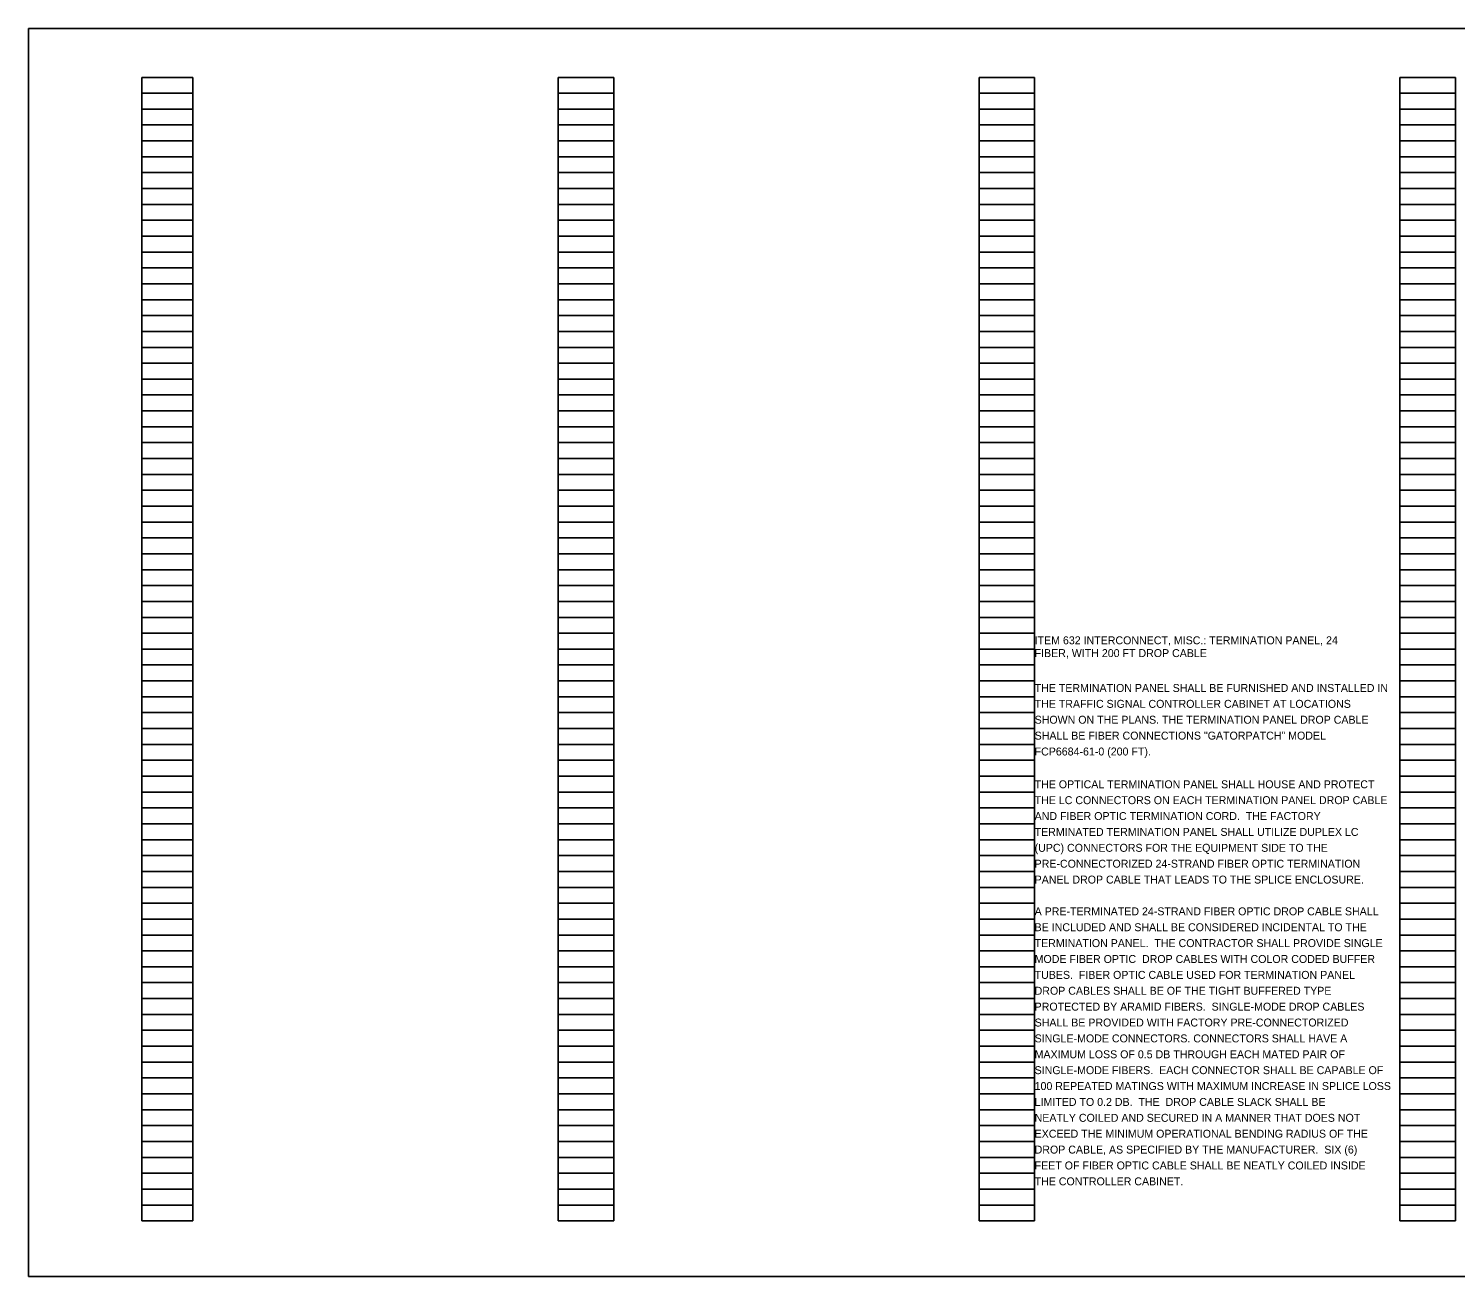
# Model space of a CAD drawing. Extents: x -36.9 to 49.6, y -47.1 to 37.
# Drawn here: x -0.51 to 24.65, y -47.06 to -25.06 of the extents above; entities that cross this region are included whole.
import ezdxf

# ---------------------------------------------------------------- set-up
doc = ezdxf.new("R2010")
doc.units = 0
for name, color, linetype in [('SC_Scratch1', 7, 'Continuous'), ('SH_Cut_Line', 7, 'Continuous'), ('SH_Data', 7, 'Continuous'), ('SH_Text', 7, 'Continuous')]:
    doc.layers.add(name, color=color, linetype=linetype)

msp = doc.modelspace()

# ---------------------------------------------------------------- linework, layer by layer
at = {"layer": 'SC_Scratch1'}
for p, q in [((1.494, -46.083), (1.494, -25.923)), ((1.494, -25.923), (2.394, -25.923)), ((2.394, -46.083), (2.394, -25.923)), ((8.834, -46.083), (8.834, -25.923)), ((8.834, -25.923), (9.814, -25.923)), ((9.814, -46.083), (9.814, -25.923)), ((16.254, -46.083), (16.254, -25.923)), ((16.254, -25.923), (17.234, -25.923)), ((17.234, -46.083), (17.234, -25.923)), ((23.674, -46.083), (23.674, -25.923)), ((23.674, -25.923), (24.654, -25.923)), ((24.654, -46.083), (24.654, -25.923)), ((1.494, -26.203), (2.394, -26.203)), ((8.834, -26.203), (9.814, -26.203)), ((16.254, -26.203), (17.234, -26.203)), ((23.674, -26.203), (24.654, -26.203)), ((1.494, -26.483), (2.394, -26.483)), ((8.834, -26.483), (9.814, -26.483)), ((16.254, -26.483), (17.234, -26.483)), ((23.674, -26.483), (24.654, -26.483)), ((1.494, -26.763), (2.394, -26.763)), ((8.834, -26.763), (9.814, -26.763)), ((16.254, -26.763), (17.234, -26.763)), ((23.674, -26.763), (24.654, -26.763)), ((1.494, -27.043), (2.394, -27.043)), ((8.834, -27.043), (9.814, -27.043)), ((16.254, -27.043), (17.234, -27.043)), ((23.674, -27.043), (24.654, -27.043)), ((1.494, -27.323), (2.394, -27.323)), ((8.834, -27.323), (9.814, -27.323)), ((16.254, -27.323), (17.234, -27.323)), ((23.674, -27.323), (24.654, -27.323)), ((1.494, -27.603), (2.394, -27.603)), ((8.834, -27.603), (9.814, -27.603)), ((16.254, -27.603), (17.234, -27.603)), ((23.674, -27.603), (24.654, -27.603)), ((1.494, -27.883), (2.394, -27.883)), ((8.834, -27.883), (9.814, -27.883)), ((16.254, -27.883), (17.234, -27.883)), ((23.674, -27.883), (24.654, -27.883)), ((1.494, -28.163), (2.394, -28.163)), ((8.834, -28.163), (9.814, -28.163)), ((16.254, -28.163), (17.234, -28.163)), ((23.674, -28.163), (24.654, -28.163)), ((1.494, -28.443), (2.394, -28.443)), ((8.834, -28.443), (9.814, -28.443)), ((16.254, -28.443), (17.234, -28.443)), ((23.674, -28.443), (24.654, -28.443)), ((1.494, -28.723), (2.394, -28.723)), ((8.834, -28.723), (9.814, -28.723)), ((16.254, -28.723), (17.234, -28.723)), ((23.674, -28.723), (24.654, -28.723)), ((1.494, -29.003), (2.394, -29.003)), ((8.834, -29.003), (9.814, -29.003)), ((16.254, -29.003), (17.234, -29.003)), ((23.674, -29.003), (24.654, -29.003)), ((1.494, -29.283), (2.394, -29.283)), ((8.834, -29.283), (9.814, -29.283)), ((16.254, -29.283), (17.234, -29.283)), ((23.674, -29.283), (24.654, -29.283)), ((1.494, -29.563), (2.394, -29.563)), ((8.834, -29.563), (9.814, -29.563)), ((16.254, -29.563), (17.234, -29.563)), ((23.674, -29.563), (24.654, -29.563)), ((1.494, -29.843), (2.394, -29.843)), ((8.834, -29.843), (9.814, -29.843)), ((16.254, -29.843), (17.234, -29.843)), ((23.674, -29.843), (24.654, -29.843)), ((1.494, -30.123), (2.394, -30.123)), ((8.834, -30.123), (9.814, -30.123)), ((16.254, -30.123), (17.234, -30.123)), ((23.674, -30.123), (24.654, -30.123)), ((1.494, -30.403), (2.394, -30.403)), ((8.834, -30.403), (9.814, -30.403)), ((16.254, -30.403), (17.234, -30.403)), ((23.674, -30.403), (24.654, -30.403)), ((1.494, -30.683), (2.394, -30.683)), ((8.834, -30.683), (9.814, -30.683)), ((16.254, -30.683), (17.234, -30.683)), ((23.674, -30.683), (24.654, -30.683)), ((1.494, -30.963), (2.394, -30.963)), ((8.834, -30.963), (9.814, -30.963)), ((16.254, -30.963), (17.234, -30.963)), ((23.674, -30.963), (24.654, -30.963)), ((1.494, -31.243), (2.394, -31.243)), ((8.834, -31.243), (9.814, -31.243)), ((16.254, -31.243), (17.234, -31.243)), ((23.674, -31.243), (24.654, -31.243)), ((1.494, -31.523), (2.394, -31.523)), ((8.834, -31.523), (9.814, -31.523)), ((16.254, -31.523), (17.234, -31.523)), ((23.674, -31.523), (24.654, -31.523)), ((1.494, -31.803), (2.394, -31.803)), ((8.834, -31.803), (9.814, -31.803)), ((16.254, -31.803), (17.234, -31.803)), ((23.674, -31.803), (24.654, -31.803)), ((1.494, -32.083), (2.394, -32.083)), ((8.834, -32.083), (9.814, -32.083)), ((16.254, -32.083), (17.234, -32.083)), ((23.674, -32.083), (24.654, -32.083)), ((1.494, -32.363), (2.394, -32.363)), ((8.834, -32.363), (9.814, -32.363)), ((16.254, -32.363), (17.234, -32.363)), ((23.674, -32.363), (24.654, -32.363)), ((1.494, -32.643), (2.394, -32.643)), ((8.834, -32.643), (9.814, -32.643)), ((16.254, -32.643), (17.234, -32.643)), ((23.674, -32.643), (24.654, -32.643)), ((1.494, -32.923), (2.394, -32.923)), ((8.834, -32.923), (9.814, -32.923)), ((16.254, -32.923), (17.234, -32.923)), ((23.674, -32.923), (24.654, -32.923)), ((1.494, -33.203), (2.394, -33.203)), ((8.834, -33.203), (9.814, -33.203)), ((16.254, -33.203), (17.234, -33.203)), ((23.674, -33.203), (24.654, -33.203)), ((1.494, -33.483), (2.394, -33.483)), ((8.834, -33.483), (9.814, -33.483)), ((16.254, -33.483), (17.234, -33.483)), ((23.674, -33.483), (24.654, -33.483)), ((1.494, -33.763), (2.394, -33.763)), ((8.834, -33.763), (9.814, -33.763)), ((16.254, -33.763), (17.234, -33.763)), ((23.674, -33.763), (24.654, -33.763)), ((1.494, -34.043), (2.394, -34.043)), ((8.834, -34.043), (9.814, -34.043)), ((16.254, -34.043), (17.234, -34.043)), ((23.674, -34.043), (24.654, -34.043)), ((1.494, -34.323), (2.394, -34.323)), ((8.834, -34.323), (9.814, -34.323)), ((16.254, -34.323), (17.234, -34.323)), ((23.674, -34.323), (24.654, -34.323)), ((1.494, -34.603), (2.394, -34.603)), ((8.834, -34.603), (9.814, -34.603)), ((16.254, -34.603), (17.234, -34.603)), ((23.674, -34.603), (24.654, -34.603)), ((1.494, -34.883), (2.394, -34.883)), ((8.834, -34.883), (9.814, -34.883)), ((16.254, -34.883), (17.234, -34.883)), ((23.674, -34.883), (24.654, -34.883)), ((1.494, -35.163), (2.394, -35.163)), ((8.834, -35.163), (9.814, -35.163)), ((16.254, -35.163), (17.234, -35.163)), ((23.674, -35.163), (24.654, -35.163)), ((1.494, -35.443), (2.394, -35.443)), ((8.834, -35.443), (9.814, -35.443)), ((16.254, -35.443), (17.234, -35.443)), ((23.674, -35.443), (24.654, -35.443)), ((1.494, -35.723), (2.394, -35.723)), ((8.834, -35.723), (9.814, -35.723)), ((16.254, -35.723), (17.234, -35.723)), ((23.674, -35.723), (24.654, -35.723)), ((1.494, -36.003), (2.394, -36.003)), ((8.834, -36.003), (9.814, -36.003)), ((16.254, -36.003), (17.234, -36.003)), ((23.674, -36.003), (24.654, -36.003)), ((1.494, -36.283), (2.394, -36.283)), ((8.834, -36.283), (9.814, -36.283)), ((16.254, -36.283), (17.234, -36.283)), ((23.674, -36.283), (24.654, -36.283)), ((1.494, -36.563), (2.394, -36.563)), ((8.834, -36.563), (9.814, -36.563)), ((16.254, -36.563), (17.234, -36.563)), ((23.674, -36.563), (24.654, -36.563)), ((1.494, -36.843), (2.394, -36.843)), ((8.834, -36.843), (9.814, -36.843)), ((16.254, -36.843), (17.234, -36.843)), ((23.674, -36.843), (24.654, -36.843)), ((1.494, -37.123), (2.394, -37.123)), ((8.834, -37.123), (9.814, -37.123)), ((16.254, -37.123), (17.234, -37.123)), ((23.674, -37.123), (24.654, -37.123)), ((1.494, -37.403), (2.394, -37.403)), ((8.834, -37.403), (9.814, -37.403)), ((16.254, -37.403), (17.234, -37.403)), ((23.674, -37.403), (24.654, -37.403)), ((1.494, -37.683), (2.394, -37.683)), ((8.834, -37.683), (9.814, -37.683)), ((16.254, -37.683), (17.234, -37.683)), ((23.674, -37.683), (24.654, -37.683)), ((1.494, -37.963), (2.394, -37.963)), ((8.834, -37.963), (9.814, -37.963)), ((16.254, -37.963), (17.234, -37.963)), ((23.674, -37.963), (24.654, -37.963)), ((1.494, -38.243), (2.394, -38.243)), ((8.834, -38.243), (9.814, -38.243)), ((16.254, -38.243), (17.234, -38.243)), ((23.674, -38.243), (24.654, -38.243)), ((1.494, -38.523), (2.394, -38.523)), ((8.834, -38.523), (9.814, -38.523)), ((16.254, -38.523), (17.234, -38.523)), ((23.674, -38.523), (24.654, -38.523)), ((1.494, -38.803), (2.394, -38.803)), ((8.834, -38.803), (9.814, -38.803)), ((16.254, -38.803), (17.234, -38.803)), ((23.674, -38.803), (24.654, -38.803)), ((1.494, -39.083), (2.394, -39.083)), ((8.834, -39.083), (9.814, -39.083)), ((16.254, -39.083), (17.234, -39.083)), ((23.674, -39.083), (24.654, -39.083)), ((1.494, -39.363), (2.394, -39.363)), ((8.834, -39.363), (9.814, -39.363)), ((16.254, -39.363), (17.234, -39.363)), ((23.674, -39.363), (24.654, -39.363)), ((1.494, -39.643), (2.394, -39.643)), ((8.834, -39.643), (9.814, -39.643)), ((16.254, -39.643), (17.234, -39.643)), ((23.674, -39.643), (24.654, -39.643)), ((1.494, -39.923), (2.394, -39.923)), ((8.834, -39.923), (9.814, -39.923)), ((16.254, -39.923), (17.234, -39.923)), ((23.674, -39.923), (24.654, -39.923)), ((1.494, -40.203), (2.394, -40.203)), ((8.834, -40.203), (9.814, -40.203)), ((16.254, -40.203), (17.234, -40.203)), ((23.674, -40.203), (24.654, -40.203)), ((1.494, -40.483), (2.394, -40.483)), ((8.834, -40.483), (9.814, -40.483)), ((16.254, -40.483), (17.234, -40.483)), ((23.674, -40.483), (24.654, -40.483)), ((1.494, -40.763), (2.394, -40.763)), ((8.834, -40.763), (9.814, -40.763)), ((16.254, -40.763), (17.234, -40.763)), ((23.674, -40.763), (24.654, -40.763)), ((1.494, -41.043), (2.394, -41.043)), ((8.834, -41.043), (9.814, -41.043)), ((16.254, -41.043), (17.234, -41.043)), ((23.674, -41.043), (24.654, -41.043)), ((1.494, -41.323), (2.394, -41.323)), ((8.834, -41.323), (9.814, -41.323)), ((16.254, -41.323), (17.234, -41.323)), ((23.674, -41.323), (24.654, -41.323)), ((1.494, -41.603), (2.394, -41.603)), ((8.834, -41.603), (9.814, -41.603)), ((16.254, -41.603), (17.234, -41.603)), ((23.674, -41.603), (24.654, -41.603)), ((1.494, -41.883), (2.394, -41.883)), ((8.834, -41.883), (9.814, -41.883)), ((16.254, -41.883), (17.234, -41.883)), ((23.674, -41.883), (24.654, -41.883)), ((1.494, -42.163), (2.394, -42.163)), ((8.834, -42.163), (9.814, -42.163)), ((16.254, -42.163), (17.234, -42.163)), ((23.674, -42.163), (24.654, -42.163)), ((1.494, -42.443), (2.394, -42.443)), ((8.834, -42.443), (9.814, -42.443)), ((16.254, -42.443), (17.234, -42.443)), ((23.674, -42.443), (24.654, -42.443)), ((1.494, -42.723), (2.394, -42.723)), ((8.834, -42.723), (9.814, -42.723)), ((16.254, -42.723), (17.234, -42.723)), ((23.674, -42.723), (24.654, -42.723)), ((1.494, -43.003), (2.394, -43.003)), ((8.834, -43.003), (9.814, -43.003)), ((16.254, -43.003), (17.234, -43.003)), ((23.674, -43.003), (24.654, -43.003)), ((1.494, -43.283), (2.394, -43.283)), ((8.834, -43.283), (9.814, -43.283)), ((16.254, -43.283), (17.234, -43.283)), ((23.674, -43.283), (24.654, -43.283)), ((1.494, -43.563), (2.394, -43.563)), ((8.834, -43.563), (9.814, -43.563)), ((16.254, -43.563), (17.234, -43.563)), ((23.674, -43.563), (24.654, -43.563)), ((1.494, -43.843), (2.394, -43.843)), ((8.834, -43.843), (9.814, -43.843)), ((16.254, -43.843), (17.234, -43.843)), ((23.674, -43.843), (24.654, -43.843)), ((1.494, -44.123), (2.394, -44.123)), ((8.834, -44.123), (9.814, -44.123)), ((16.254, -44.123), (17.234, -44.123)), ((23.674, -44.123), (24.654, -44.123)), ((1.494, -44.403), (2.394, -44.403)), ((8.834, -44.403), (9.814, -44.403)), ((16.254, -44.403), (17.234, -44.403)), ((23.674, -44.403), (24.654, -44.403)), ((1.494, -44.683), (2.394, -44.683)), ((8.834, -44.683), (9.814, -44.683)), ((16.254, -44.683), (17.234, -44.683)), ((23.674, -44.683), (24.654, -44.683)), ((1.494, -44.963), (2.394, -44.963)), ((8.834, -44.963), (9.814, -44.963)), ((16.254, -44.963), (17.234, -44.963)), ((23.674, -44.963), (24.654, -44.963)), ((1.494, -45.243), (2.394, -45.243)), ((8.834, -45.243), (9.814, -45.243)), ((16.254, -45.243), (17.234, -45.243)), ((23.674, -45.243), (24.654, -45.243)), ((1.494, -45.523), (2.394, -45.523)), ((8.834, -45.523), (9.814, -45.523)), ((16.254, -45.523), (17.234, -45.523)), ((23.674, -45.523), (24.654, -45.523)), ((1.494, -45.803), (2.394, -45.803)), ((8.834, -45.803), (9.814, -45.803)), ((16.254, -45.803), (17.234, -45.803)), ((23.674, -45.803), (24.654, -45.803)), ((1.494, -46.083), (2.394, -46.083)), ((8.834, -46.083), (9.814, -46.083)), ((16.254, -46.083), (17.234, -46.083)), ((23.674, -46.083), (24.654, -46.083)), ((-0.506, -47.063), (-0.506, -47.063))]:
    msp.add_line(p, q, dxfattribs=at)
at = {"layer": 'SH_Cut_Line'}
msp.add_lwpolyline([(-0.506, -47.063), (33.494, -47.063), (33.494, -25.063), (-0.506, -25.063)], close=True, dxfattribs=at)

# ---------------------------------------------------------------- texts
at = {"layer": 'SH_Data'}
for s, p in [('ITEM 632 INTERCONNECT, MISC.: TERMINATION PANEL, 24 ', (17.234, -35.918)), ('FIBER, WITH 200 FT DROP CABLE', (17.234, -36.143))]:
    msp.add_text(s, height=0.14, dxfattribs=at).set_placement(p)
at = {"layer": 'SH_Text'}
for s, p in [('THE TERMINATION PANEL SHALL BE FURNISHED AND INSTALLED IN ', (17.234, -36.758)), ('THE TRAFFIC SIGNAL CONTROLLER CABINET AT LOCATIONS ', (17.234, -37.038)), ('SHOWN ON THE PLANS. THE TERMINATION PANEL DROP CABLE ', (17.234, -37.318)), ('SHALL BE FIBER CONNECTIONS "GATORPATCH" MODEL ', (17.234, -37.598)), ('FCP6684-61-0 (200 FT).', (17.234, -37.878)), ('THE OPTICAL TERMINATION PANEL SHALL HOUSE AND PROTECT ', (17.234, -38.456)), ('THE LC CONNECTORS ON EACH TERMINATION PANEL DROP CABLE ', (17.234, -38.736)), ('AND FIBER OPTIC TERMINATION CORD.  THE FACTORY ', (17.234, -39.016)), ('TERMINATED TERMINATION PANEL SHALL UTILIZE DUPLEX LC ', (17.234, -39.296)), ('(UPC) CONNECTORS FOR THE EQUIPMENT SIDE TO THE ', (17.234, -39.576)), ('PRE-CONNECTORIZED 24-STRAND FIBER OPTIC TERMINATION ', (17.234, -39.856)), ('PANEL DROP CABLE THAT LEADS TO THE SPLICE ENCLOSURE.', (17.234, -40.136)), ('A PRE-TERMINATED 24-STRAND FIBER OPTIC DROP CABLE SHALL ', (17.234, -40.696)), ('BE INCLUDED AND SHALL BE CONSIDERED INCIDENTAL TO THE ', (17.234, -40.976)), ('TERMINATION PANEL.  THE CONTRACTOR SHALL PROVIDE SINGLE ', (17.234, -41.256)), ('MODE FIBER OPTIC  DROP CABLES WITH COLOR CODED BUFFER ', (17.234, -41.536)), ('TUBES.  FIBER OPTIC CABLE USED FOR TERMINATION PANEL ', (17.234, -41.816)), ('DROP CABLES SHALL BE OF THE TIGHT BUFFERED TYPE ', (17.234, -42.096)), ('PROTECTED BY ARAMID FIBERS.  SINGLE-MODE DROP CABLES ', (17.234, -42.376)), ('SHALL BE PROVIDED WITH FACTORY PRE-CONNECTORIZED ', (17.234, -42.656)), ('SINGLE-MODE CONNECTORS. CONNECTORS SHALL HAVE A ', (17.234, -42.936)), ('MAXIMUM LOSS OF 0.5 DB THROUGH EACH MATED PAIR OF ', (17.234, -43.216)), ('SINGLE-MODE FIBERS.  EACH CONNECTOR SHALL BE CAPABLE OF ', (17.234, -43.496)), ('100 REPEATED MATINGS WITH MAXIMUM INCREASE IN SPLICE LOSS ', (17.234, -43.776)), ('LIMITED TO 0.2 DB.  THE  DROP CABLE SLACK SHALL BE ', (17.234, -44.056)), ('NEATLY COILED AND SECURED IN A MANNER THAT DOES NOT ', (17.234, -44.336)), ('EXCEED THE MINIMUM OPERATIONAL BENDING RADIUS OF THE ', (17.234, -44.616)), ('DROP CABLE, AS SPECIFIED BY THE MANUFACTURER.  SIX (6) ', (17.234, -44.896)), ('FEET OF FIBER OPTIC CABLE SHALL BE NEATLY COILED INSIDE ', (17.234, -45.176)), ('THE CONTROLLER CABINET.', (17.234, -45.456))]:
    msp.add_text(s, height=0.14, dxfattribs=at).set_placement(p)

doc.saveas('drawing.dxf')
